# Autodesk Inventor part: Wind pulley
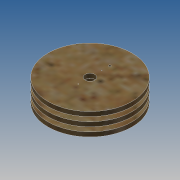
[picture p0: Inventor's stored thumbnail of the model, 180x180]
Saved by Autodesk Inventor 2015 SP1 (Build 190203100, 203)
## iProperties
Created: 2015-01
Part Number: Wind pulley
Material: Generic
Document SubType Name: Modeling
Designer: Steve Brooks
Density: 1 g/cm^3
Appearance: IDS MDF
Author: Steve Brooks
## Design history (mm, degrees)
sketch "Sketch1"
  geometry: L1 (28.282, 12.632)-(28.282, 12.642); L2 (28.282, 44.382)-(28.282, 44.392); L3 (28.282, 56.188)-(28.282, 56.178); C1 r 25.4 at (28.282, 28.512); C2 r 57.15 at (28.282, 28.512); C3 r 6.747 at (28.282, 28.512); 3 further points; 2 other entities
  constraints: 6 end point, 3 centre point, 4 other
  dimensions: "d1" = 114.3 diameter of C2
extrude "Extrusion1" new body sketch "Sketch1" distance "d3" = 6; taper "d4" = 0 deg
sketch "Sketch2"
  geometry: L1 (-336.3, 106.482)-(-336.3, 106.492); L2 (-329.278, 81.586)-(-329.278, 81.596); L3 (-329.278, 49.836)-(-329.278, 49.846); L4 (0, 15.87)-(0, 15.88); L5 (0, -15.88)-(0, -15.87); C1 r 25.4 at (-329.278, 65.716); C2 r 6.747 at (-327.348, 105.831); C3 r 6.747 at (-329.278, 65.716); C4 r 25.4 at (0, 0); C5 r 6.747 at (0, 0); C6 r 12.7 at (-328.718, -142.004); 8 further points; 7 other entities
  constraints: 10 end point, 6 centre point, 14 other
extrude "Extrusion2" new body sketch "Sketch2" distance "d5" = 6; taper "d6" = 0 deg
sketch "Sketch3"
  geometry: C1 r 6.747 at (0, 0) reference; C2 r 0.508 at (0, -15.875) reference; C3 r 0.508 at (0, 15.875) reference; C4 r 57.15 at (0, 0) reference; 1 further point
extrude "Extrusion3" new body sketch "Sketch3" distance "d7" = 6; taper "d8" = 0 deg
sketch "Sketch4"
  geometry: C1 r 6.747 at (0, 0) reference; C2 r 0.508 at (0, 15.875) reference; C3 r 0.508 at (0, -15.875) reference; C4 r 25.4 at (0, 0) reference; 1 further point
extrude "Extrusion4" new body sketch "Sketch4" distance "d9" = 6; taper "d10" = 0 deg
sketch "Sketch5"
  geometry: C1 r 6.747 at (0, 0) reference; C2 r 0.508 at (0, -15.875) reference; C3 r 0.508 at (0, 15.875) reference; C4 r 57.15 at (0, 0) reference; 1 further point
extrude "Extrusion5" new body sketch "Sketch5" distance "d11" = 6; taper "d12" = 0 deg
sketch "Sketch6"
  geometry: C1 r 6.747 at (0, 0) reference; 2 further points
  dimensions: "d13" = 27 distance of C1.centre point (0, 27)
hole "Hole1" sketch "Sketch6" at (0, 27) diameter "d14" = 3; stored, may be unused: countersink angle "d18" = 90 deg, drill point angle "d20" = 118 deg; dims "d15" = 6, "d16" = 4, "d17" = 2, "d19" = 8
sketch "Sketch7"
  geometry: C1 r 1.5 at (0, 27) reference; 1 further point
hole "Hole2" sketch "Sketch7" at (0, 27) diameter "d21" = 3; stored, may be unused: countersink angle "d25" = 90 deg, drill point angle "d27" = 118 deg; dims "d22" = 6, "d23" = 4, "d24" = 2, "d26" = 8
sketch "Sketch8"
  geometry: C1 r 1.5 at (0, 27) reference; 1 further point
hole "Hole3" sketch "Sketch8" at (0, 27) diameter "d28" = 3; stored, may be unused: countersink angle "d32" = 90 deg, drill point angle "d34" = 118 deg; dims "d29" = 6, "d30" = 4, "d31" = 2, "d33" = 8
body "Solid1"
body "Solid2"
body "Solid3"
body "Solid4"
body "Solid5"
